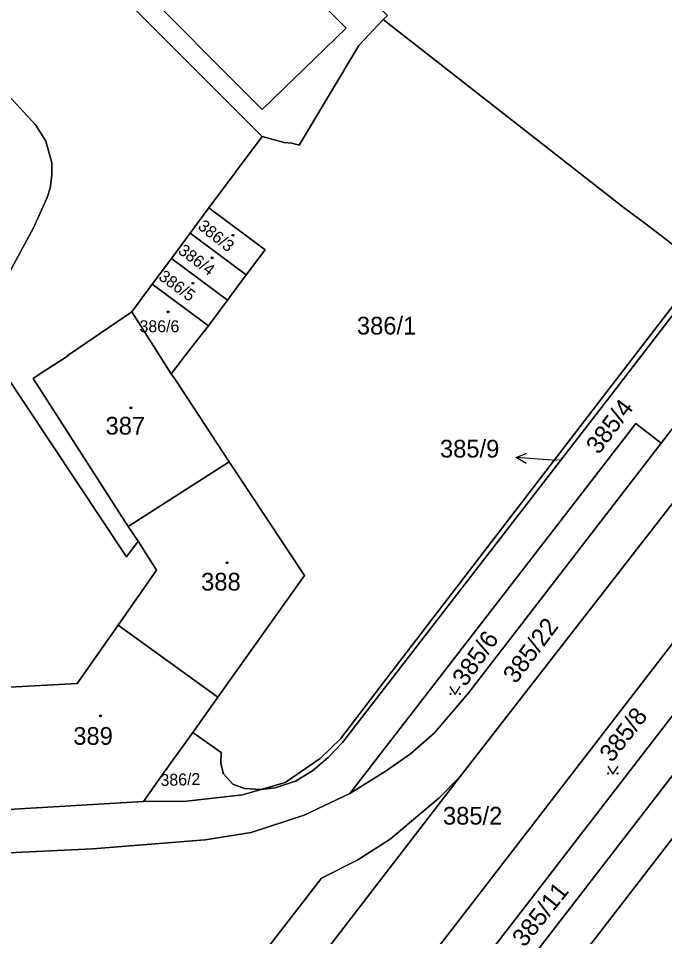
# Model space of a CAD drawing. Extents: x -598934 to -598196, y -1162208 to -1161502.
# Drawn here: x -598826.6 to -598764.6, y -1162016.6 to -1161928.6 of the extents above; entities that cross this region are included whole.
import ezdxf

# ---------------------------------------------------------------- set-up
doc = ezdxf.new("R2010")
doc.units = 0
for name, color, linetype in [('KN_CAR_KR', 7, 'Continuous'), ('KN_KULTURY', 7, 'Continuous'), ('KN_PARC_CIS_POM', 7, 'Continuous'), ('KN_PARC_CIS_POZ', 7, 'Continuous'), ('KN_PARC_CIS_STAV', 7, 'Continuous'), ('KN_PARC_PLOCHA', 7, 'Continuous'), ('PARC_C_SIPKA', 7, 'Continuous'), ('parcely_l', 7, 'Continuous')]:
    doc.layers.add(name, color=color, linetype=linetype)

msp = doc.modelspace()

# ---------------------------------------------------------------- linework, layer by layer
at = {"layer": 'KN_CAR_KR'}
for points in [[(-598807.99, -1161916.61), (-598795.14, -1161929.52)], [(-598803.21, -1161937.3), (-598816.02, -1161924.42)], [(-598795.14, -1161929.52), (-598803.21, -1161937.3)]]:
    msp.add_lwpolyline(points, dxfattribs=at)
at = {"layer": 'KN_KULTURY'}
for points in [[(-598785.212, -1161992.612), (-598784.712, -1161993.362), (-598784.212, -1161992.612)], [(-598770.092, -1162000.242), (-598769.592, -1162000.992), (-598769.092, -1162000.242)]]:
    msp.add_lwpolyline(points, dxfattribs=at)
for centre, radius in [((-598806.01, -1161949.36), 0.09), ((-598806.01, -1161949.36), 0.0398), ((-598808, -1161951.52), 0.09), ((-598808, -1161951.52), 0.0398), ((-598809.83, -1161953.96), 0.09), ((-598809.83, -1161953.96), 0.0398), ((-598812.22, -1161956.7), 0.09), ((-598812.22, -1161956.7), 0.0398), ((-598815.78, -1161965.89), 0.09), ((-598815.78, -1161965.89), 0.0398), ((-598806.55, -1161980.74), 0.09), ((-598806.55, -1161980.74), 0.0398), ((-598785.162, -1161993.311), 0.05), ((-598784.263, -1161993.311), 0.05), ((-598818.68, -1161995.41), 0.09), ((-598818.68, -1161995.41), 0.0398), ((-598770.042, -1162000.941), 0.05), ((-598769.143, -1162000.941), 0.05)]:
    msp.add_circle(centre, radius, dxfattribs=at)
at = {"layer": 'KN_PARC_PLOCHA'}
for points in [[(-598817.27, -1161925.78), (-598803.2, -1161939.89), (-598808.3, -1161946.74), (-598810.1, -1161949.16), (-598811.9, -1161951.59), (-598813.73, -1161954.04), (-598815.7, -1161956.69), (-598821.69, -1161960.8), (-598821.95, -1161961.02), (-598824.44, -1161962.6), (-598825.14, -1161963.08), (-598816.04, -1161977.27), (-598815.09, -1161978.66), (-598816.21, -1161980.17), (-598830.55, -1161958.62), (-598825.15, -1161948.72), (-598823.81, -1161945.75), (-598823.52, -1161944.84), (-598823.35, -1161943.59), (-598823.36, -1161942.42), (-598823.93, -1161940.34), (-598824.89, -1161938.81), (-598887.13, -1161871.41)], [(-598887.13, -1161871.41), (-598824.89, -1161938.81), (-598823.93, -1161940.34), (-598823.36, -1161942.42), (-598823.35, -1161943.59), (-598823.52, -1161944.84), (-598823.81, -1161945.75), (-598825.15, -1161948.72), (-598830.55, -1161958.62), (-598816.21, -1161980.17), (-598815.09, -1161978.66), (-598813.32, -1161981.44), (-598816.98, -1161986.74), (-598820.93, -1161992.32), (-598829.17, -1161992.77)], [(-598736.42, -1161926.53), (-598733.97, -1161929.15), (-598731.03, -1161932.2), (-598731.93, -1161933.4), (-598731.65, -1161933.61), (-598784.24, -1162001.22), (-598786.26, -1162003.29), (-598788.46, -1162005.15), (-598790.94, -1162007.24), (-598794.04, -1162009.21), (-598797.52, -1162010.97), (-598804.91, -1162020.57)], [(-598738.52, -1161927.42), (-598739.72, -1161928.9), (-598740.06, -1161929.16), (-598740.57, -1161929.39), (-598741.06, -1161929.5), (-598741.54, -1161929.51), (-598742.22, -1161929.33), (-598742.84, -1161928.96), (-598742.99, -1161929.21), (-598747.68, -1161935.13), (-598761.02, -1161952.44), (-598766.41, -1161948.3), (-598768.47, -1161946.75), (-598791.6, -1161928.67), (-598791.18, -1161928.31)], [(-598828.63, -1162004.44), (-598814.58, -1162003.63), (-598810.45, -1162003.58), (-598805.09, -1162002.99), (-598803.3, -1162002.48), (-598801.94, -1162002.33), (-598800, -1162001.69), (-598798.39, -1162000.7), (-598796.88, -1161999.4), (-598795.5, -1161997.96), (-598770.15, -1161965.15), (-598747.65, -1161935.96)], [(-598805.25, -1162042.08), (-598784.14, -1162014.75), (-598725.73, -1161939.03), (-598725.15, -1161938.28), (-598722.36, -1161941.17), (-598725.91, -1161945.8), (-598734.6, -1161957.45), (-598746.07, -1161972.32), (-598751.1, -1161978.85), (-598781.01, -1162017.58)], [(-598779.24, -1162021.04), (-598747.68, -1161980.16), (-598748.97, -1161979.37), (-598751.1, -1161978.85), (-598746.07, -1161972.32), (-598745.12, -1161974.36), (-598744.11, -1161975.57), (-598729.49, -1161956.43), (-598731.99, -1161956.81), (-598734.6, -1161957.45), (-598725.91, -1161945.8), (-598725.77, -1161947.64), (-598725.25, -1161949.06), (-598721.69, -1161952.15), (-598722.71, -1161953.41), (-598724.6, -1161955.73), (-598726.08, -1161957.55), (-598726.95, -1161959.02), (-598735.88, -1161970.42), (-598740.07, -1161975.77), (-598741.35, -1161977.6), (-598744.94, -1161982.47), (-598747.09, -1161985.38), (-598801.66, -1162056.1)], [(-598761.87, -1161965.27), (-598764.96, -1161969.29), (-598767.41, -1161967.41), (-598794.79, -1162002.85), (-598799.16, -1162004.93), (-598804.24, -1162006.6), (-598808.67, -1162007.3), (-598819.47, -1162008.16), (-598850.4, -1162009.63)], [(-598850.4, -1162009.63), (-598819.47, -1162008.16), (-598808.67, -1162007.3), (-598804.24, -1162006.6), (-598799.16, -1162004.93), (-598794.79, -1162002.85), (-598791.32, -1162000.69), (-598789, -1161999.07), (-598786.7, -1161997.06), (-598783.5, -1161993.32), (-598764.96, -1161969.29), (-598761.87, -1161965.27)], [(-598801.66, -1162056.1), (-598747.09, -1161985.38)]]:
    msp.add_lwpolyline(points, dxfattribs=at)
for points in [[(-598791.6, -1161928.67), (-598793.94, -1161931.18), (-598799.64, -1161940.73), (-598800.34, -1161940.54), (-598801.08, -1161940.48), (-598803.2, -1161939.89), (-598817.27, -1161925.78), (-598816.02, -1161924.42), (-598807.99, -1161916.61), (-598805.37, -1161914.05), (-598799.89, -1161919.53), (-598798.35, -1161921.13), (-598791.18, -1161928.31)], [(-598761.02, -1161952.44), (-598770.63, -1161964.93), (-598791.38, -1161991.95), (-598795.7, -1161997.63), (-598797.65, -1161999.51), (-598801.01, -1162001.82), (-598803.3, -1162002.48), (-598804.9, -1162002.38), (-598806.01, -1162001.96), (-598806.9, -1162000.97), (-598807.17, -1161999.98), (-598807.12, -1161998.94), (-598809.85, -1161997.02), (-598807.43, -1161993.63), (-598799.14, -1161981.98), (-598806.37, -1161971.07), (-598811.5, -1161963.22), (-598811.91, -1161962.64), (-598809.91, -1161960.02), (-598808.35, -1161958.03), (-598806.53, -1161955.59), (-598804.72, -1161953.16), (-598802.92, -1161950.74), (-598808.3, -1161946.74), (-598803.2, -1161939.89), (-598801.08, -1161940.48), (-598800.34, -1161940.54), (-598799.64, -1161940.73), (-598793.94, -1161931.18), (-598791.6, -1161928.67), (-598768.47, -1161946.75), (-598766.41, -1161948.3)], [(-598803.3, -1162002.48), (-598801.01, -1162001.82), (-598797.65, -1161999.51), (-598795.7, -1161997.63), (-598791.38, -1161991.95), (-598770.63, -1161964.93), (-598761.02, -1161952.44), (-598747.68, -1161935.13), (-598742.99, -1161929.21), (-598747.65, -1161935.96), (-598770.15, -1161965.15), (-598795.5, -1161997.96), (-598796.88, -1161999.4), (-598798.39, -1162000.7), (-598800, -1162001.69), (-598801.94, -1162002.33)], [(-598725.15, -1161938.28), (-598725.73, -1161939.03), (-598784.14, -1162014.75), (-598805.25, -1162042.08), (-598805.73, -1162041.71), (-598824.9, -1162066.06), (-598829.3, -1162071.75), (-598834.62, -1162067.66), (-598830.2, -1162061.93), (-598819.69, -1162047.55), (-598811.67, -1162037.16), (-598811.81, -1162037.05), (-598811.38, -1162036.49), (-598784.24, -1162001.22), (-598731.65, -1161933.61), (-598731.93, -1161933.4), (-598731.03, -1161932.2)], [(-598804.72, -1161953.16), (-598810.1, -1161949.16), (-598808.3, -1161946.74), (-598802.92, -1161950.74)], [(-598804.72, -1161953.16), (-598806.53, -1161955.59), (-598811.9, -1161951.59), (-598810.1, -1161949.16)], [(-598806.53, -1161955.59), (-598808.35, -1161958.03), (-598813.73, -1161954.04), (-598811.9, -1161951.59)], [(-598808.35, -1161958.03), (-598809.91, -1161960.02), (-598811.91, -1161962.64), (-598815.7, -1161956.69), (-598813.73, -1161954.04)], [(-598811.91, -1161962.64), (-598811.5, -1161963.22), (-598806.37, -1161971.07), (-598816.04, -1161977.27), (-598825.14, -1161963.08), (-598824.44, -1161962.6), (-598821.95, -1161961.02), (-598821.69, -1161960.8), (-598815.7, -1161956.69)], [(-598764.96, -1161969.29), (-598783.5, -1161993.32), (-598786.7, -1161997.06), (-598789, -1161999.07), (-598791.32, -1162000.69), (-598794.79, -1162002.85), (-598767.41, -1161967.41)], [(-598807.43, -1161993.63), (-598816.98, -1161986.74), (-598813.32, -1161981.44), (-598815.09, -1161978.66), (-598816.04, -1161977.27), (-598806.37, -1161971.07), (-598799.14, -1161981.98)], [(-598801.77, -1162044.56), (-598781.01, -1162017.58), (-598751.1, -1161978.85), (-598748.97, -1161979.37), (-598747.68, -1161980.16), (-598779.24, -1162021.04), (-598798.16, -1162045.56)], [(-598807.43, -1161993.63), (-598809.85, -1161997.02), (-598812.6, -1162000.8), (-598814.58, -1162003.63), (-598828.63, -1162004.44), (-598829.17, -1161992.77), (-598820.93, -1161992.32), (-598816.98, -1161986.74)], [(-598803.3, -1162002.48), (-598805.09, -1162002.99), (-598810.45, -1162003.58), (-598814.58, -1162003.63), (-598812.6, -1162000.8), (-598809.85, -1161997.02), (-598807.12, -1161998.94), (-598807.17, -1161999.98), (-598806.9, -1162000.97), (-598806.01, -1162001.96), (-598804.9, -1162002.38)], [(-598811.81, -1162037.05), (-598812.61, -1162036.32), (-598813.4, -1162035.12), (-598813.67, -1162034), (-598813.64, -1162032.95), (-598813.45, -1162031.95), (-598813, -1162031.05), (-598812.41, -1162031.47), (-598804.33, -1162021.01), (-598804.91, -1162020.57), (-598797.52, -1162010.97), (-598794.04, -1162009.21), (-598790.94, -1162007.24), (-598788.46, -1162005.15), (-598786.26, -1162003.29), (-598784.24, -1162001.22), (-598811.38, -1162036.49)]]:
    msp.add_lwpolyline(points, close=True, dxfattribs=at)
at = {"layer": 'PARC_C_SIPKA'}
for points in [[(-598777.913, -1161971.235), (-598778.871, -1161970.66), (-598777.836, -1161970.238)], [(-598774.95, -1161970.96), (-598775.88, -1161970.89), (-598778.871, -1161970.66)]]:
    msp.add_lwpolyline(points, dxfattribs=at)
at = {"layer": 'parcely_l'}
for points in [[(-598906.75, -1161860.04), (-598893.09, -1161874.87), (-598889.28, -1161871.31), (-598888.87, -1161871.08), (-598888.33, -1161870.94), (-598887.58, -1161871.09), (-598887.13, -1161871.41), (-598824.89, -1161938.81), (-598823.93, -1161940.34), (-598823.36, -1161942.42), (-598823.35, -1161943.59), (-598823.52, -1161944.84), (-598823.81, -1161945.75), (-598825.15, -1161948.72), (-598830.55, -1161958.62), (-598816.21, -1161980.17), (-598815.09, -1161978.66)], [(-598805.37, -1161914.05), (-598799.89, -1161919.53), (-598798.35, -1161921.13), (-598791.18, -1161928.31), (-598791.6, -1161928.67)], [(-598817.27, -1161925.78), (-598803.2, -1161939.89)], [(-598742.99, -1161929.21), (-598747.65, -1161935.96), (-598770.15, -1161965.15), (-598795.5, -1161997.96), (-598796.88, -1161999.4), (-598798.39, -1162000.7), (-598800, -1162001.69), (-598801.94, -1162002.33), (-598803.3, -1162002.48)], [(-598803.2, -1161939.89), (-598801.08, -1161940.48), (-598800.34, -1161940.54), (-598799.64, -1161940.73), (-598793.94, -1161931.18), (-598791.6, -1161928.67)], [(-598791.6, -1161928.67), (-598768.47, -1161946.75), (-598766.41, -1161948.3), (-598761.02, -1161952.44)], [(-598731.03, -1161932.2), (-598731.93, -1161933.4), (-598731.65, -1161933.61), (-598784.24, -1162001.22)], [(-598824.9, -1162066.06), (-598805.73, -1162041.71), (-598805.25, -1162042.08), (-598784.14, -1162014.75), (-598725.73, -1161939.03), (-598725.15, -1161938.28)], [(-598808.3, -1161946.74), (-598803.2, -1161939.89)], [(-598810.1, -1161949.16), (-598808.3, -1161946.74)], [(-598808.3, -1161946.74), (-598802.92, -1161950.74), (-598804.72, -1161953.16)], [(-598811.9, -1161951.59), (-598810.1, -1161949.16)], [(-598804.72, -1161953.16), (-598810.1, -1161949.16)], [(-598813.73, -1161954.04), (-598811.9, -1161951.59)], [(-598811.9, -1161951.59), (-598806.53, -1161955.59)], [(-598761.02, -1161952.44), (-598770.63, -1161964.93), (-598791.38, -1161991.95), (-598795.7, -1161997.63), (-598797.65, -1161999.51), (-598801.01, -1162001.82), (-598803.3, -1162002.48)], [(-598806.53, -1161955.59), (-598804.72, -1161953.16)], [(-598815.7, -1161956.69), (-598813.73, -1161954.04)], [(-598813.73, -1161954.04), (-598808.35, -1161958.03)], [(-598806.53, -1161955.59), (-598808.35, -1161958.03)], [(-598816.04, -1161977.27), (-598825.14, -1161963.08), (-598824.44, -1161962.6), (-598821.95, -1161961.02), (-598821.69, -1161960.8), (-598815.7, -1161956.69)], [(-598811.91, -1161962.64), (-598815.7, -1161956.69)], [(-598808.35, -1161958.03), (-598809.91, -1161960.02), (-598811.91, -1161962.64)], [(-598811.91, -1161962.64), (-598811.5, -1161963.22), (-598806.37, -1161971.07)], [(-598764.96, -1161969.29), (-598761.87, -1161965.27)], [(-598764.96, -1161969.29), (-598767.41, -1161967.41), (-598794.79, -1162002.85)], [(-598794.79, -1162002.85), (-598791.32, -1162000.69), (-598789, -1161999.07), (-598786.7, -1161997.06), (-598783.5, -1161993.32), (-598764.96, -1161969.29)], [(-598816.04, -1161977.27), (-598806.37, -1161971.07)], [(-598806.37, -1161971.07), (-598799.14, -1161981.98), (-598807.43, -1161993.63)], [(-598815.09, -1161978.66), (-598816.04, -1161977.27)], [(-598816.98, -1161986.74), (-598813.32, -1161981.44), (-598815.09, -1161978.66)], [(-598801.77, -1162044.56), (-598798.16, -1162045.56), (-598779.24, -1162021.04), (-598747.68, -1161980.16), (-598748.97, -1161979.37), (-598751.1, -1161978.85)], [(-598751.1, -1161978.85), (-598781.01, -1162017.58), (-598801.77, -1162044.56)], [(-598744.94, -1161982.47), (-598747.09, -1161985.38), (-598801.66, -1162056.1), (-598803.76, -1162058.8)], [(-598816.98, -1161986.74), (-598820.93, -1161992.32), (-598829.17, -1161992.77)], [(-598807.43, -1161993.63), (-598816.98, -1161986.74)], [(-598809.85, -1161997.02), (-598807.43, -1161993.63)], [(-598814.58, -1162003.63), (-598812.6, -1162000.8), (-598809.85, -1161997.02)], [(-598809.85, -1161997.02), (-598807.12, -1161998.94), (-598807.17, -1161999.98), (-598806.9, -1162000.97), (-598806.01, -1162001.96), (-598804.9, -1162002.38), (-598803.3, -1162002.48)], [(-598784.24, -1162001.22), (-598786.26, -1162003.29), (-598788.46, -1162005.15), (-598790.94, -1162007.24), (-598794.04, -1162009.21), (-598797.52, -1162010.97), (-598804.91, -1162020.57), (-598804.33, -1162021.01), (-598812.41, -1162031.47), (-598813, -1162031.05), (-598813.45, -1162031.95), (-598813.64, -1162032.95), (-598813.67, -1162034), (-598813.4, -1162035.12), (-598812.61, -1162036.32), (-598811.81, -1162037.05)], [(-598784.24, -1162001.22), (-598811.38, -1162036.49), (-598811.81, -1162037.05)], [(-598870.88, -1162006.95), (-598870.22, -1162007.65), (-598869.42, -1162008.38), (-598866.85, -1162009.75), (-598865.83, -1162009.95), (-598864.79, -1162009.98), (-598850.4, -1162009.63), (-598819.47, -1162008.16), (-598808.67, -1162007.3), (-598804.24, -1162006.6), (-598799.16, -1162004.93), (-598794.79, -1162002.85)], [(-598803.3, -1162002.48), (-598805.09, -1162002.99), (-598810.45, -1162003.58), (-598814.58, -1162003.63)], [(-598828.63, -1162004.44), (-598814.58, -1162003.63)]]:
    msp.add_lwpolyline(points, dxfattribs=at)

# ---------------------------------------------------------------- texts
at = {"layer": 'KN_PARC_CIS_POM'}
msp.add_text('385/9', height=0.2, dxfattribs=at).set_placement((-598775.167, -1161970.96))
at = {"layer": 'KN_PARC_CIS_POZ'}
for s, p in [('386/1', (-598794.122, -1161958.87)), ('385/9', (-598786.162, -1161970.66)), ('385/2', (-598785.877, -1162005.84))]:
    msp.add_text(s, height=1.7, dxfattribs=at).set_placement(p)
for s, height, rotation, p in [('385/4', 1.7, 53.10017, (-598770.946, -1161970.453)), ('385/22', 1.7, 53.10044, (-598778.901, -1161992.423)), ('385/6', 1.7, 54.89941, (-598783.729, -1161992.707)), ('385/8', 1.7, 52.19986, (-598769.679, -1161999.965)), ('386/2', 1.14, 1.73522, (-598812.924, -1162002.147)), ('385/11', 1.7, 51.30036, (-598778.067, -1162017.669))]:
    msp.add_text(s, height=height, rotation=rotation, dxfattribs=at).set_placement(p)
at = {"layer": 'KN_PARC_CIS_STAV'}
for s, rotation, p in [('386/3', 321.32685, (-598809.442, -1161948.656)), ('386/4', 323.31439, (-598811.332, -1161951.022)), ('386/5', 323.85352, (-598813.207, -1161953.52))]:
    msp.add_text(s, height=1.14, rotation=rotation, dxfattribs=at).set_placement(p)
for s, height, p in [('386/6', 1.14, (-598814.95, -1161958.65)), ('387', 1.7, (-598818.207, -1161968.46)), ('388', 1.7, (-598809.047, -1161983.41)), ('389', 1.7, (-598821.297, -1161998.19))]:
    msp.add_text(s, height=height, dxfattribs=at).set_placement(p)

doc.saveas('drawing.dxf')
